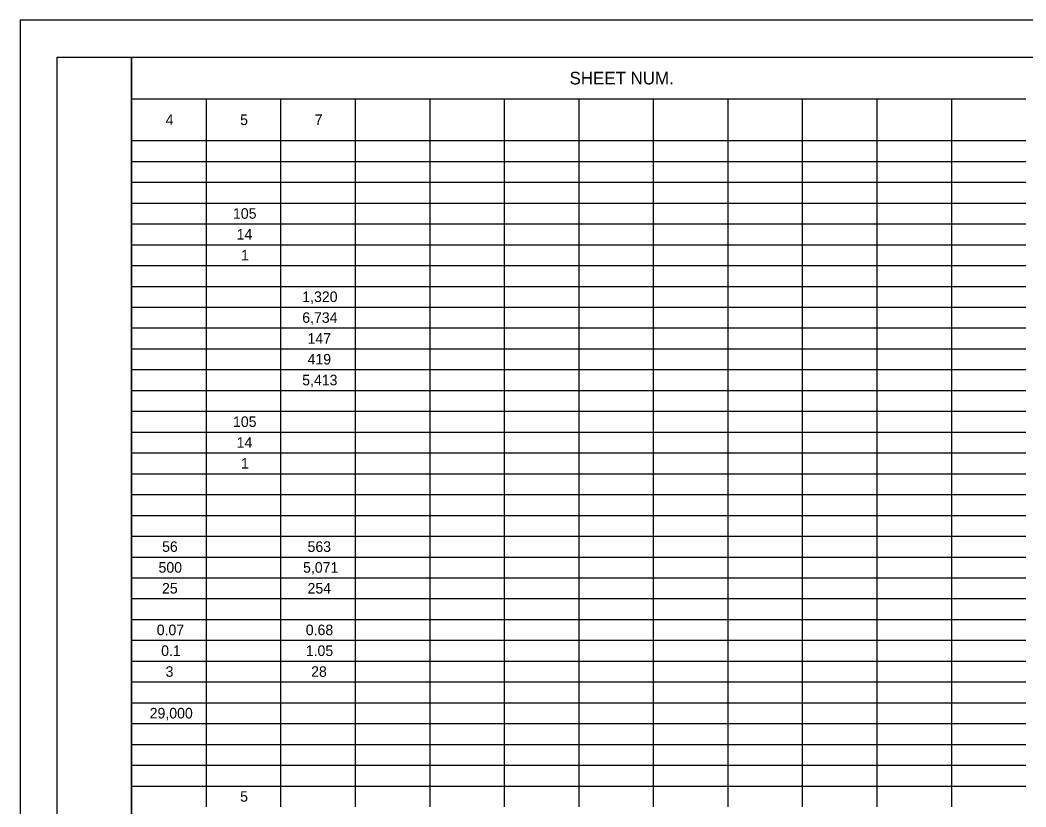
# Model space of a CAD drawing. Extents: x 0 to 34, y 0 to 22.
# Drawn here: x 0 to 13.53, y 11.42 to 22 of the extents above; entities that cross this region are included whole.
import ezdxf

# ---------------------------------------------------------------- set-up
doc = ezdxf.new("R2010")
doc.units = 0
for name, color, linetype in [('Default', 7, 'Continuous'), ('SH_Border', 7, 'Continuous'), ('SH_Cut_Line', 7, 'Continuous')]:
    doc.layers.add(name, color=color, linetype=linetype)

msp = doc.modelspace()

# ---------------------------------------------------------------- linework, layer by layer
at = {"layer": 'Default'}
for p, q in [((1.5, 21.5), (6.513, 21.5)), ((1.5, 21.5), (1.5, 21.22)), ((6.513, 21.5), (7.515, 21.5)), ((7.515, 21.5), (12.528, 21.5)), ((12.528, 21.5), (13.531, 21.5)), ((1.5, 21.22), (1.5, 20.94)), ((1.5, 20.94), (6.513, 20.94)), ((1.5, 20.94), (1.5, 20.66)), ((2.503, 20.94), (2.503, 20.66)), ((3.505, 20.94), (3.505, 20.66)), ((4.508, 20.94), (4.508, 20.66)), ((5.51, 20.94), (5.51, 20.66)), ((6.513, 20.94), (7.515, 20.94)), ((6.513, 20.94), (6.513, 20.66)), ((7.515, 20.94), (12.528, 20.94)), ((7.515, 20.94), (7.515, 20.66)), ((8.518, 20.94), (8.518, 20.66)), ((9.52, 20.94), (9.52, 20.66)), ((10.523, 20.94), (10.523, 20.66)), ((11.525, 20.94), (11.525, 20.66)), ((12.528, 20.94), (13.531, 20.94)), ((12.528, 20.94), (12.528, 20.66)), ((1.5, 20.66), (1.5, 20.38)), ((2.503, 20.66), (2.503, 20.38)), ((3.505, 20.66), (3.505, 20.38)), ((4.508, 20.66), (4.508, 20.38)), ((5.51, 20.66), (5.51, 20.38)), ((6.513, 20.66), (6.513, 20.38)), ((7.515, 20.66), (7.515, 20.38)), ((8.518, 20.66), (8.518, 20.38)), ((9.52, 20.66), (9.52, 20.38)), ((10.523, 20.66), (10.523, 20.38)), ((11.525, 20.66), (11.525, 20.38)), ((12.528, 20.66), (12.528, 20.38)), ((1.5, 20.38), (6.513, 20.38)), ((1.5, 20.38), (1.5, 20.1)), ((2.503, 20.38), (2.503, 20.1)), ((3.505, 20.38), (3.505, 20.1)), ((4.508, 20.38), (4.508, 20.1)), ((5.51, 20.38), (5.51, 20.1)), ((6.513, 20.38), (7.515, 20.38)), ((6.513, 20.38), (6.513, 20.1)), ((7.515, 20.38), (12.528, 20.38)), ((7.515, 20.38), (7.515, 20.1)), ((8.518, 20.38), (8.518, 20.1)), ((9.52, 20.38), (9.52, 20.1)), ((10.523, 20.38), (10.523, 20.1)), ((11.525, 20.38), (11.525, 20.1)), ((12.528, 20.38), (13.531, 20.38)), ((12.528, 20.38), (12.528, 20.1)), ((1.5, 20.1), (6.513, 20.1)), ((1.5, 20.1), (1.5, 18.7)), ((2.503, 20.1), (2.503, 18.7)), ((3.505, 20.1), (3.505, 18.7)), ((4.508, 20.1), (4.508, 18.7)), ((5.51, 20.1), (5.51, 18.7)), ((6.513, 20.1), (7.515, 20.1)), ((6.513, 20.1), (6.513, 18.7)), ((7.515, 20.1), (12.528, 20.1)), ((7.515, 20.1), (7.515, 18.7)), ((8.518, 20.1), (8.518, 18.7)), ((9.52, 20.1), (9.52, 18.7)), ((10.523, 20.1), (10.523, 18.7)), ((11.525, 20.1), (11.525, 18.7)), ((12.528, 20.1), (13.531, 20.1)), ((12.528, 20.1), (12.528, 18.7)), ((1.5, 19.82), (6.513, 19.82)), ((6.513, 19.82), (7.515, 19.82)), ((7.515, 19.82), (12.528, 19.82)), ((12.528, 19.82), (13.531, 19.82)), ((1.5, 19.54), (6.513, 19.54)), ((6.513, 19.54), (7.515, 19.54)), ((7.515, 19.54), (12.528, 19.54)), ((12.528, 19.54), (13.531, 19.54)), ((1.5, 19.26), (6.513, 19.26)), ((6.513, 19.26), (7.515, 19.26)), ((7.515, 19.26), (12.528, 19.26)), ((12.528, 19.26), (13.531, 19.26)), ((1.5, 18.98), (6.513, 18.98)), ((6.513, 18.98), (7.515, 18.98)), ((7.515, 18.98), (12.528, 18.98)), ((12.528, 18.98), (13.531, 18.98)), ((1.5, 18.7), (6.513, 18.7)), ((1.5, 18.7), (1.5, 18.14)), ((2.503, 18.7), (2.503, 18.14)), ((3.505, 18.7), (3.505, 18.14)), ((4.508, 18.7), (4.508, 18.14)), ((5.51, 18.7), (5.51, 18.14)), ((6.513, 18.7), (7.515, 18.7)), ((6.513, 18.7), (6.513, 18.14)), ((7.515, 18.7), (12.528, 18.7)), ((7.515, 18.7), (7.515, 18.14)), ((8.518, 18.7), (8.518, 18.14)), ((9.52, 18.7), (9.52, 18.14)), ((10.523, 18.7), (10.523, 18.14)), ((11.525, 18.7), (11.525, 18.14)), ((12.528, 18.7), (13.531, 18.7)), ((12.528, 18.7), (12.528, 18.14)), ((1.5, 18.42), (6.513, 18.42)), ((6.513, 18.42), (7.515, 18.42)), ((7.515, 18.42), (12.528, 18.42)), ((12.528, 18.42), (13.531, 18.42)), ((1.5, 18.14), (6.513, 18.14)), ((1.5, 18.14), (1.5, 17.86)), ((2.503, 18.14), (2.503, 17.86)), ((3.505, 18.14), (3.505, 17.86)), ((4.508, 18.14), (4.508, 17.86)), ((5.51, 18.14), (5.51, 17.86)), ((6.513, 18.14), (7.515, 18.14)), ((6.513, 18.14), (6.513, 17.86)), ((7.515, 18.14), (12.528, 18.14)), ((7.515, 18.14), (7.515, 17.86)), ((8.518, 18.14), (8.518, 17.86)), ((9.52, 18.14), (9.52, 17.86)), ((10.523, 18.14), (10.523, 17.86)), ((11.525, 18.14), (11.525, 17.86)), ((12.528, 18.14), (13.531, 18.14)), ((12.528, 18.14), (12.528, 17.86)), ((1.5, 17.86), (6.513, 17.86)), ((1.5, 17.86), (1.5, 17.58)), ((2.503, 17.86), (2.503, 17.58)), ((3.505, 17.86), (3.505, 17.58)), ((4.508, 17.86), (4.508, 17.58)), ((5.51, 17.86), (5.51, 17.58)), ((6.513, 17.86), (7.515, 17.86)), ((6.513, 17.86), (6.513, 17.58)), ((7.515, 17.86), (12.528, 17.86)), ((7.515, 17.86), (7.515, 17.58)), ((8.518, 17.86), (8.518, 17.58)), ((9.52, 17.86), (9.52, 17.58)), ((10.523, 17.86), (10.523, 17.58)), ((11.525, 17.86), (11.525, 17.58)), ((12.528, 17.86), (13.531, 17.86)), ((12.528, 17.86), (12.528, 17.58)), ((1.5, 17.58), (6.513, 17.58)), ((1.5, 17.58), (1.5, 17.3)), ((2.503, 17.58), (2.503, 17.3)), ((3.505, 17.58), (3.505, 17.3)), ((4.508, 17.58), (4.508, 17.3)), ((5.51, 17.58), (5.51, 17.3)), ((6.513, 17.58), (7.515, 17.58)), ((6.513, 17.58), (6.513, 17.3)), ((7.515, 17.58), (12.528, 17.58)), ((7.515, 17.58), (7.515, 17.3)), ((8.518, 17.58), (8.518, 17.3)), ((9.52, 17.58), (9.52, 17.3)), ((10.523, 17.58), (10.523, 17.3)), ((11.525, 17.58), (11.525, 17.3)), ((12.528, 17.58), (13.531, 17.58)), ((12.528, 17.58), (12.528, 17.3)), ((1.5, 17.3), (6.513, 17.3)), ((1.5, 17.3), (1.5, 17.02)), ((2.503, 17.3), (2.503, 17.02)), ((3.505, 17.3), (3.505, 17.02)), ((4.508, 17.3), (4.508, 17.02)), ((5.51, 17.3), (5.51, 17.02)), ((6.513, 17.3), (7.515, 17.3)), ((6.513, 17.3), (6.513, 17.02)), ((7.515, 17.3), (12.528, 17.3)), ((7.515, 17.3), (7.515, 17.02)), ((8.518, 17.3), (8.518, 17.02)), ((9.52, 17.3), (9.52, 17.02)), ((10.523, 17.3), (10.523, 17.02)), ((11.525, 17.3), (11.525, 17.02)), ((12.528, 17.3), (13.531, 17.3)), ((12.528, 17.3), (12.528, 17.02)), ((1.5, 17.02), (6.513, 17.02)), ((1.5, 17.02), (1.5, 16.74)), ((2.503, 17.02), (2.503, 16.74)), ((3.505, 17.02), (3.505, 16.74)), ((4.508, 17.02), (4.508, 16.74)), ((5.51, 17.02), (5.51, 16.74)), ((6.513, 17.02), (7.515, 17.02)), ((6.513, 17.02), (6.513, 16.74)), ((7.515, 17.02), (12.528, 17.02)), ((7.515, 17.02), (7.515, 16.74)), ((8.518, 17.02), (8.518, 16.74)), ((9.52, 17.02), (9.52, 16.74)), ((10.523, 17.02), (10.523, 16.74)), ((11.525, 17.02), (11.525, 16.74)), ((12.528, 17.02), (13.531, 17.02)), ((12.528, 17.02), (12.528, 16.74)), ((1.5, 16.74), (6.513, 16.74)), ((1.5, 16.74), (1.5, 16.18)), ((2.503, 16.74), (2.503, 16.18)), ((3.505, 16.74), (3.505, 16.18)), ((4.508, 16.74), (4.508, 16.18)), ((5.51, 16.74), (5.51, 16.18)), ((6.513, 16.74), (7.515, 16.74)), ((6.513, 16.74), (6.513, 16.18)), ((7.515, 16.74), (12.528, 16.74)), ((7.515, 16.74), (7.515, 16.18)), ((8.518, 16.74), (8.518, 16.18)), ((9.52, 16.74), (9.52, 16.18)), ((10.523, 16.74), (10.523, 16.18)), ((11.525, 16.74), (11.525, 16.18)), ((12.528, 16.74), (13.531, 16.74)), ((12.528, 16.74), (12.528, 16.18)), ((1.5, 16.46), (6.513, 16.46)), ((6.513, 16.46), (7.515, 16.46)), ((7.515, 16.46), (12.528, 16.46)), ((12.528, 16.46), (13.531, 16.46)), ((1.5, 16.18), (6.513, 16.18)), ((1.5, 16.18), (1.5, 15.9)), ((2.503, 16.18), (2.503, 15.9)), ((3.505, 16.18), (3.505, 15.9)), ((4.508, 16.18), (4.508, 15.9)), ((5.51, 16.18), (5.51, 15.9)), ((6.513, 16.18), (7.515, 16.18)), ((6.513, 16.18), (6.513, 15.9)), ((7.515, 16.18), (12.528, 16.18)), ((7.515, 16.18), (7.515, 15.9)), ((8.518, 16.18), (8.518, 15.9)), ((9.52, 16.18), (9.52, 15.9)), ((10.523, 16.18), (10.523, 15.9)), ((11.525, 16.18), (11.525, 15.9)), ((12.528, 16.18), (13.531, 16.18)), ((12.528, 16.18), (12.528, 15.9)), ((1.5, 15.9), (6.513, 15.9)), ((1.5, 15.9), (1.5, 15.62)), ((2.503, 15.9), (2.503, 15.62)), ((3.505, 15.9), (3.505, 15.62)), ((4.508, 15.9), (4.508, 15.62)), ((5.51, 15.9), (5.51, 15.62)), ((6.513, 15.9), (7.515, 15.9)), ((6.513, 15.9), (6.513, 15.62)), ((7.515, 15.9), (12.528, 15.9)), ((7.515, 15.9), (7.515, 15.62)), ((8.518, 15.9), (8.518, 15.62)), ((9.52, 15.9), (9.52, 15.62)), ((10.523, 15.9), (10.523, 15.62)), ((11.525, 15.9), (11.525, 15.62)), ((12.528, 15.9), (13.531, 15.9)), ((12.528, 15.9), (12.528, 15.62)), ((1.5, 15.62), (6.513, 15.62)), ((1.5, 15.62), (1.5, 15.34)), ((2.503, 15.62), (2.503, 15.34)), ((3.505, 15.62), (3.505, 15.34)), ((4.508, 15.62), (4.508, 15.34)), ((5.51, 15.62), (5.51, 15.34)), ((6.513, 15.62), (7.515, 15.62)), ((6.513, 15.62), (6.513, 15.34)), ((7.515, 15.62), (12.528, 15.62)), ((7.515, 15.62), (7.515, 15.34)), ((8.518, 15.62), (8.518, 15.34)), ((9.52, 15.62), (9.52, 15.34)), ((10.523, 15.62), (10.523, 15.34)), ((11.525, 15.62), (11.525, 15.34)), ((12.528, 15.62), (13.531, 15.62)), ((12.528, 15.62), (12.528, 15.34)), ((1.5, 15.34), (6.513, 15.34)), ((1.5, 15.34), (1.5, 14.78)), ((2.503, 15.34), (2.503, 14.78)), ((3.505, 15.34), (3.505, 14.78)), ((4.508, 15.34), (4.508, 14.78)), ((5.51, 15.34), (5.51, 14.78)), ((6.513, 15.34), (7.515, 15.34)), ((6.513, 15.34), (6.513, 14.78)), ((7.515, 15.34), (12.528, 15.34)), ((7.515, 15.34), (7.515, 14.78)), ((8.518, 15.34), (8.518, 14.78)), ((9.52, 15.34), (9.52, 14.78)), ((10.523, 15.34), (10.523, 14.78)), ((11.525, 15.34), (11.525, 14.78)), ((12.528, 15.34), (13.531, 15.34)), ((12.528, 15.34), (12.528, 14.78)), ((1.5, 15.06), (6.513, 15.06)), ((6.513, 15.06), (7.515, 15.06)), ((7.515, 15.06), (12.528, 15.06)), ((12.528, 15.06), (13.531, 15.06)), ((1.5, 14.78), (6.513, 14.78)), ((1.5, 14.78), (1.5, 14.5)), ((2.503, 14.78), (2.503, 14.5)), ((3.505, 14.78), (3.505, 14.5)), ((4.508, 14.78), (4.508, 14.5)), ((5.51, 14.78), (5.51, 14.5)), ((6.513, 14.78), (7.515, 14.78)), ((6.513, 14.78), (6.513, 14.5)), ((7.515, 14.78), (12.528, 14.78)), ((7.515, 14.78), (7.515, 14.5)), ((8.518, 14.78), (8.518, 14.5)), ((9.52, 14.78), (9.52, 14.5)), ((10.523, 14.78), (10.523, 14.5)), ((11.525, 14.78), (11.525, 14.5)), ((12.528, 14.78), (13.531, 14.78)), ((12.528, 14.78), (12.528, 14.5)), ((1.5, 14.5), (6.513, 14.5)), ((1.5, 14.5), (1.5, 14.22)), ((2.503, 14.5), (2.503, 14.22)), ((3.505, 14.5), (3.505, 14.22)), ((4.508, 14.5), (4.508, 14.22)), ((5.51, 14.5), (5.51, 14.22)), ((6.513, 14.5), (7.515, 14.5)), ((6.513, 14.5), (6.513, 14.22)), ((7.515, 14.5), (12.528, 14.5)), ((7.515, 14.5), (7.515, 14.22)), ((8.518, 14.5), (8.518, 14.22)), ((9.52, 14.5), (9.52, 14.22)), ((10.523, 14.5), (10.523, 14.22)), ((11.525, 14.5), (11.525, 14.22)), ((12.528, 14.5), (13.531, 14.5)), ((12.528, 14.5), (12.528, 14.22)), ((1.5, 14.22), (6.513, 14.22)), ((1.5, 14.22), (1.5, 13.94)), ((2.503, 14.22), (2.503, 13.94)), ((3.505, 14.22), (3.505, 13.94)), ((4.508, 14.22), (4.508, 13.94)), ((5.51, 14.22), (5.51, 13.94)), ((6.513, 14.22), (7.515, 14.22)), ((6.513, 14.22), (6.513, 13.94)), ((7.515, 14.22), (12.528, 14.22)), ((7.515, 14.22), (7.515, 13.94)), ((8.518, 14.22), (8.518, 13.94)), ((9.52, 14.22), (9.52, 13.94)), ((10.523, 14.22), (10.523, 13.94)), ((11.525, 14.22), (11.525, 13.94)), ((12.528, 14.22), (13.531, 14.22)), ((12.528, 14.22), (12.528, 13.94)), ((1.5, 13.94), (6.513, 13.94)), ((1.5, 13.94), (1.5, 11.7)), ((2.503, 13.94), (2.503, 11.7)), ((3.505, 13.94), (3.505, 11.7)), ((4.508, 13.94), (4.508, 11.7)), ((5.51, 13.94), (5.51, 11.7)), ((6.513, 13.94), (7.515, 13.94)), ((6.513, 13.94), (6.513, 11.7)), ((7.515, 13.94), (12.528, 13.94)), ((7.515, 13.94), (7.515, 11.7)), ((8.518, 13.94), (8.518, 11.7)), ((9.52, 13.94), (9.52, 11.7)), ((10.523, 13.94), (10.523, 11.7)), ((11.525, 13.94), (11.525, 11.7)), ((12.528, 13.94), (13.531, 13.94)), ((12.528, 13.94), (12.528, 11.7)), ((1.5, 13.66), (6.513, 13.66)), ((6.513, 13.66), (7.515, 13.66)), ((7.515, 13.66), (12.528, 13.66)), ((12.528, 13.66), (13.531, 13.66)), ((1.5, 13.38), (6.513, 13.38)), ((6.513, 13.38), (7.515, 13.38)), ((7.515, 13.38), (12.528, 13.38)), ((12.528, 13.38), (13.531, 13.38)), ((1.5, 13.1), (6.513, 13.1)), ((6.513, 13.1), (7.515, 13.1)), ((7.515, 13.1), (12.528, 13.1)), ((12.528, 13.1), (13.531, 13.1)), ((1.5, 12.82), (6.513, 12.82)), ((6.513, 12.82), (7.515, 12.82)), ((7.515, 12.82), (12.528, 12.82)), ((12.528, 12.82), (13.531, 12.82)), ((1.5, 12.54), (6.513, 12.54)), ((6.513, 12.54), (7.515, 12.54)), ((7.515, 12.54), (12.528, 12.54)), ((12.528, 12.54), (13.531, 12.54)), ((1.5, 12.26), (6.513, 12.26)), ((6.513, 12.26), (7.515, 12.26)), ((7.515, 12.26), (12.528, 12.26)), ((12.528, 12.26), (13.531, 12.26)), ((1.5, 11.98), (6.513, 11.98)), ((6.513, 11.98), (7.515, 11.98)), ((7.515, 11.98), (12.528, 11.98)), ((12.528, 11.98), (13.531, 11.98)), ((1.5, 11.7), (6.513, 11.7)), ((1.5, 11.7), (1.5, 11.42)), ((2.503, 11.7), (2.503, 11.42)), ((3.505, 11.7), (3.505, 11.42)), ((4.508, 11.7), (4.508, 11.42)), ((5.51, 11.7), (5.51, 11.42)), ((6.513, 11.7), (7.515, 11.7)), ((6.513, 11.7), (6.513, 11.42)), ((7.515, 11.7), (12.528, 11.7)), ((7.515, 11.7), (7.515, 11.42)), ((8.518, 11.7), (8.518, 11.42)), ((9.52, 11.7), (9.52, 11.42)), ((10.523, 11.7), (10.523, 11.42)), ((11.525, 11.7), (11.525, 11.42)), ((12.528, 11.7), (13.531, 11.7)), ((12.528, 11.7), (12.528, 11.42))]:
    msp.add_line(p, q, dxfattribs=at)
at = {"layer": 'SH_Border'}
for points in [[(0.5, 21.5), (1.5, 21.5), (1.5, 0.5), (0.5, 0.5)], [(1.5, 21.5), (33.5, 21.5), (33.5, 0.5), (1.5, 0.5)]]:
    msp.add_lwpolyline(points, close=True, dxfattribs=at)
at = {"layer": 'SH_Cut_Line'}
msp.add_lwpolyline([(0, 0), (34, 0), (34, 22), (0, 22)], close=True, dxfattribs=at)

# ---------------------------------------------------------------- texts
at = {"layer": 'Default'}
for s, height, p in [('SHEET NUM.', 0.17, (7.392, 21.135)), ('4', 0.142, (1.958, 20.589)), ('5', 0.142, (2.96, 20.589)), ('7', 0.142, (3.963, 20.589)), ('105', 0.1417, (2.864, 19.329)), ('14', 0.1417, (2.913, 19.049)), ('1', 0.142, (2.972, 18.769)), ('1,320', 0.1417, (3.796, 18.209)), ('6,734', 0.1417, (3.796, 17.929)), ('147', 0.1417, (3.867, 17.649)), ('419', 0.1417, (3.867, 17.369)), ('5,413', 0.1417, (3.795, 17.089)), ('105', 0.1417, (2.864, 16.529)), ('14', 0.1417, (2.913, 16.249)), ('1', 0.142, (2.972, 15.969)), ('56', 0.1417, (1.91, 14.849)), ('563', 0.1417, (3.867, 14.849)), ('500', 0.1417, (1.862, 14.569)), ('5,071', 0.1417, (3.807, 14.569)), ('25', 0.1417, (1.909, 14.289)), ('254', 0.1417, (3.867, 14.289)), ('0.07', 0.1417, (1.838, 13.729)), ('0.68', 0.1417, (3.843, 13.729)), ('0.1', 0.1417, (1.898, 13.449)), ('1.05', 0.1417, (3.843, 13.449)), ('3', 0.142, (1.957, 13.169)), ('28', 0.1417, (3.915, 13.169)), ('29,000', 0.1417, (1.743, 12.609)), ('5', 0.142, (2.96, 11.489))]:
    msp.add_text(s, height=height, dxfattribs=at).set_placement(p)

doc.saveas('drawing.dxf')
